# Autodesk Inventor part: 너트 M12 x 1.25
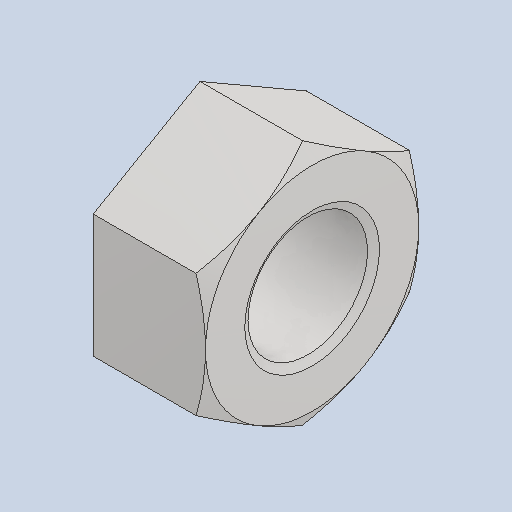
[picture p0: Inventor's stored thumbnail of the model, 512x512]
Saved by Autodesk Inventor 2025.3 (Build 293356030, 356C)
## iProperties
Created: 2025-08
Part Number: 너트 M12 x 1.25
Material: 스테인리스강
Description: 6각 너트
Document SubType Name: Modeling
Designer: user
Density: 8.08 g/cm^3
Appearance: 기본값
Sending System: Autodesk Inventor 2026
Preprocessor: ST-DEVELOPER v20.1
Author: jhkim
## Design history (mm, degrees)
sketch "스케치1"
  geometry: 1 further point
  constraints: 1 other
feature "Solid1"
node "솔리드1"
